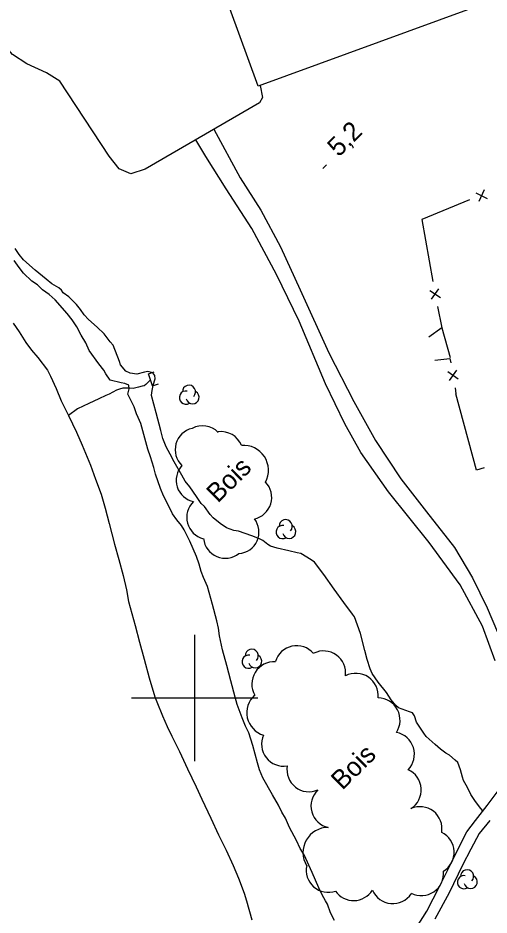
# Model space of a CAD drawing. Extents: x 381879 to 384696, y 5564785 to 5567594.
# Drawn here: x 383572 to 383646.6, y 5566565.6 to 5566707.6 of the extents above; entities that cross this region are included whole.
import ezdxf

# ---------------------------------------------------------------- set-up
doc = ezdxf.new("R2010")
doc.units = 0
for name, color, linetype in [('Niveau 19', 7, 'Continuous'), ('Niveau 2', 7, 'Continuous'), ('Niveau 26', 7, 'Continuous'), ('Niveau 3', 7, 'Continuous'), ('Niveau 31', 7, 'Continuous'), ('Niveau 37', 7, 'Continuous'), ('Niveau 4', 7, 'Continuous'), ('Niveau 44', 7, 'Continuous'), ('Niveau 52', 7, 'Continuous'), ('Niveau 61', 7, 'Continuous')]:
    doc.layers.add(name, color=color, linetype=linetype)

msp = doc.modelspace()

# ---------------------------------------------------------------- linework, layer by layer
at = {"layer": 'Niveau 19'}
for points in [[(383603.03, 5566690), (383607.21, 5566682.33), (383610.52, 5566677.19), (383613.62, 5566671.41), (383616.73, 5566664.57), (383621.28, 5566654.64), (383625.22, 5566646.9), (383628.63, 5566640.73), (383632.67, 5566634.69), (383636.74, 5566629.47), (383641.18, 5566623.8), (383644.03, 5566619.02), (383646.36, 5566614.26), (383648.86, 5566608.28)], [(383647.6, 5566605.87), (383645.59, 5566611.34), (383642.06, 5566617.87), (383637.15, 5566624.61), (383630.71, 5566632.64), (383626.34, 5566638.86), (383623.79, 5566643.39), (383620.73, 5566649.73), (383616.58, 5566659.64), (383612.99, 5566667.04), (383609.08, 5566674.28), (383605.02, 5566680.56), (383601.76, 5566685.67), (383600.18, 5566688.35)], [(383632.9, 5566560.05), (383636.76, 5566566.26), (383638.77, 5566570.13), (383640.13, 5566572.77), (383641.95, 5566576.55), (383643.13, 5566578.82), (383644.47, 5566580.6), (383646.34, 5566582.99), (383648.1, 5566585.3)], [(383646.76, 5566580.57), (383645.07, 5566578.51), (383643.76, 5566576.07), (383642.45, 5566573.52), (383640.34, 5566569.12), (383638.06, 5566564.97)]]:
    msp.add_lwpolyline(points, dxfattribs=at)
at = {"layer": 'Niveau 2'}
for points in [[(383580.07, 5566663.5), (383579.18, 5566664.13), (383578.92, 5566664.56), (383578.5, 5566664.88), (383577.39, 5566665.54), (383576.5, 5566666.25), (383574.74, 5566667.7), (383572.93, 5566669.31), (383572.23, 5566670.2), (383571.6, 5566671.15)], [(383622.16, 5566564.77), (383621.52, 5566565.99), (383621.07, 5566567.36), (383620.72, 5566567.9), (383620.2, 5566568.84), (383619.7, 5566569.95), (383618.64, 5566572.34), (383617.35, 5566575.16), (383616.74, 5566576.18), (383616.14, 5566577.44), (383615.06, 5566579.51), (383614.38, 5566580.97), (383613.84, 5566581.9), (383613.27, 5566583.03), (383612.36, 5566584.65), (383610.83, 5566587.37), (383610.26, 5566588.62), (383609.95, 5566589.7), (383609.22, 5566592.44), (383608.59, 5566594.49), (383608.06, 5566595.51), (383607.54, 5566596.84), (383606.77, 5566598.95), (383606.45, 5566600.13), (383605.77, 5566602.7), (383605.11, 5566605.13), (383604.45, 5566607.62), (383603.96, 5566609.81), (383603.81, 5566611.01), (383603.51, 5566612.2), (383602.82, 5566614.79), (383602.04, 5566617.62), (383601.41, 5566619.03), (383601.07, 5566619.99), (383600.75, 5566621.17), (383600.33, 5566622.38), (383599.26, 5566624.81), (383598.37, 5566626.6), (383597.91, 5566627.3), (383597.2, 5566628.17), (383596.52, 5566629.15), (383595.98, 5566630.25), (383595.08, 5566631.97), (383594.62, 5566633.15), (383593.83, 5566635.4), (383593.55, 5566636.47), (383593.05, 5566638.16), (383592.59, 5566639.36), (383592.27, 5566640.55), (383591.49, 5566643.45), (383591.05, 5566644.39), (383590.82, 5566644.97), (383590.46, 5566646.07), (383590.15, 5566646.61), (383589.41, 5566648.05), (383589.65, 5566648.94), (383589.57, 5566649.52), (383588.97, 5566649.76), (383588.36, 5566649.88), (383586.63, 5566650.31), (383585.93, 5566651.3), (383585.63, 5566651.86), (383584.82, 5566652.89), (383583.33, 5566654.99), (383582.79, 5566656.22), (383582.05, 5566657.43), (383581.36, 5566658.71), (383580.62, 5566659.84), (383579.82, 5566660.82), (383577.93, 5566663.01), (383576.96, 5566663.85), (383575.93, 5566664.59), (383575.12, 5566665.38), (383574.23, 5566665.97), (383572.91, 5566667.21), (383572.25, 5566668.13), (383571.45, 5566669.25)], [(383645.66, 5566582.12), (383645.33, 5566582.47), (383644.47, 5566583.59), (383643.76, 5566584.7), (383643.21, 5566585.81), (383642.6, 5566586.95), (383642.42, 5566587.45), (383642.11, 5566588.61), (383641.7, 5566589.76), (383641.28, 5566590.16), (383640.39, 5566590.92), (383639.79, 5566591.25), (383638.94, 5566591.86), (383638.08, 5566592.6), (383636.7, 5566593.88), (383636.3, 5566594.44), (383635.13, 5566596.18), (383634.81, 5566597.17), (383634.52, 5566597.61), (383634.02, 5566597.78), (383632.31, 5566598.44), (383631.86, 5566598.82), (383631.13, 5566599.7), (383630.39, 5566600.83), (383629.08, 5566602.48), (383628.15, 5566603.85), (383627.83, 5566604.59), (383627.36, 5566606.1), (383626.98, 5566607.51), (383626.27, 5566610.18), (383625.35, 5566612.81), (383625.03, 5566613.26), (383623.62, 5566615.12), (383622.13, 5566617.21), (383620.49, 5566619.54), (383618.97, 5566621.5), (383618.48, 5566621.84), (383616.83, 5566622.83), (383616.25, 5566622.98), (383614.94, 5566623.25), (383613.06, 5566623.68), (383612.04, 5566624.03), (383611.6, 5566624.28), (383610.79, 5566624.92), (383610.3, 5566625.18), (383609.08, 5566625.66), (383606.94, 5566626.37), (383606.22, 5566626.49), (383605.07, 5566626.92), (383604.05, 5566627.58), (383602.95, 5566628.49), (383602.46, 5566629.04), (383601.55, 5566630.27), (383601.03, 5566630.79), (383600.33, 5566631.89), (383599.26, 5566633.4), (383598.52, 5566634.3), (383597.96, 5566635.23), (383596.75, 5566637.37), (383596.15, 5566638.57), (383595.48, 5566639.76), (383594.99, 5566641.06), (383594.65, 5566642.33), (383593.9, 5566645.11), (383593.17, 5566647.84), (383593.24, 5566648.35), (383593.44, 5566649.48), (383593.76, 5566650.5), (383593.73, 5566651.01), (383593.38, 5566651.47), (383592.61, 5566651.64), (383592.05, 5566651.55), (383590.84, 5566651.23), (383589.78, 5566651.4), (383589.14, 5566651.7), (383588.26, 5566652.71), (383588.12, 5566653.23), (383587.13, 5566655.85), (383586.64, 5566656.38), (383585.7, 5566657.64), (383584.59, 5566658.69), (383583.21, 5566659.89), (383582.5, 5566660.61), (383581.95, 5566661.46), (383581.28, 5566662.25), (383580.07, 5566663.5)]]:
    msp.add_lwpolyline(points, dxfattribs=at)
at = {"layer": 'Niveau 26'}
for p, q in [((383592.69, 5566651.3), (383593.63, 5566651.63)), ((383593.35, 5566649.4), (383592.69, 5566651.3)), ((383593.35, 5566649.4), (383594.29, 5566649.72))]:
    msp.add_line(p, q, dxfattribs=at)
at = {"layer": 'Niveau 3'}
msp.add_line((383620.34, 5566683.78), (383620.91, 5566684.35), dxfattribs=at)
at = {"layer": 'Niveau 31'}
msp.add_lwpolyline([(383605.61, 5566709.12), (383657.84, 5566728.2), (383662.33, 5566715.9), (383610.1, 5566696.82)], close=True, dxfattribs=at)
at = {"layer": 'Niveau 37'}
for p, q in [((383644.55, 5566679.93), (383646.35, 5566679.04)), ((383645.89, 5566680.39), (383645.01, 5566678.58)), ((383643.56, 5566678.84), (383635.99, 5566675.74)), ((383635.99, 5566675.74), (383637.76, 5566665.9)), ((383637.28, 5566664.5), (383638.93, 5566663.36)), ((383637.54, 5566663.1), (383638.68, 5566664.75)), ((383640.12, 5566651.65), (383641.75, 5566650.48)), ((383640.35, 5566650.25), (383641.52, 5566651.88)), ((383641.26, 5566649.1), (383641.36, 5566648.13))]:
    msp.add_line(p, q, dxfattribs=at)
for points in [[(383638.46, 5566661.96), (383639.15, 5566658.55), (383637.08, 5566657.09)], [(383638.04, 5566653.47), (383640.43, 5566653.7), (383640.61, 5566653.04)], [(383645.87, 5566636.4), (383644.66, 5566636.03), (383641.36, 5566648.13)]]:
    msp.add_lwpolyline(points, dxfattribs=at)
at = {"layer": 'Niveau 4'}
for points in [[(383571.3, 5566659.32), (383572.25, 5566657.92), (383573.27, 5566656.27), (383574.18, 5566655.04), (383575.19, 5566653.9), (383576.73, 5566651.85), (383577.19, 5566650.94), (383578.11, 5566648.95), (383578.88, 5566647.02), (383579.82, 5566645.12), (383580.02, 5566644.7)], [(383593.02, 5566650.34), (383592.31, 5566649.59), (383592.04, 5566649.41), (383591.68, 5566649.32), (383591.14, 5566649.17), (383590.26, 5566648.98), (383589.71, 5566649.02), (383588.65, 5566649), (383588.13, 5566648.88), (383587.64, 5566648.71), (383586.5, 5566648.07), (383585.96, 5566647.87), (383584.85, 5566647.34), (383583.26, 5566646.58), (383581.47, 5566645.77), (383580.02, 5566644.7)], [(383580.02, 5566644.7), (383581.31, 5566642.04), (383582.19, 5566640), (383583.51, 5566636.83), (383584.33, 5566634.63), (383585.19, 5566632.25), (383585.83, 5566630.02), (383586.46, 5566627.6), (383587.34, 5566624.34), (383587.99, 5566621.9), (383588.67, 5566619.37), (383589.22, 5566617.08), (383589.55, 5566615.28), (383589.82, 5566614.3), (383590.58, 5566611.46), (383591.29, 5566608.81), (383592.01, 5566606.11), (383592.82, 5566603.16), (383593.69, 5566600.16), (383594.02, 5566599.38), (383594.93, 5566597.14), (383595.68, 5566595.45), (383596.41, 5566593.95), (383597.62, 5566591.5), (383598.88, 5566588.75), (383600.26, 5566585.91), (383601.15, 5566583.98), (383602.56, 5566580.96), (383603.8, 5566578.35), (383605, 5566575.88), (383606.14, 5566573.49), (383606.97, 5566571.46), (383607.86, 5566569.09), (383608.21, 5566567.9), (383609.07, 5566564.86)]]:
    msp.add_lwpolyline(points, dxfattribs=at)
at = {"layer": 'Niveau 44'}
msp.add_arc((383611.97, 5566597.65), 3.7, 131.5363, 253.3098, dxfattribs=at)
for centre, major_axis, ratio, start_param, end_param in [((383598.63, 5566647.53), (0.12, -1.04), 0.99999, 2.834597, 6.721173), ((383599.12, 5566648.45), (0.12, -1.04), 0.99999, 0.690957, 4.629966), ((383599.68, 5566647.57), (0.12, -1.04), 0.99999, 4.847526, 8.817401), ((383600.38, 5566639.28), (1.25, -3.22), 0.998771, 2.994381, 5.150465), ((383601.28, 5566639.62), (-2.9, 1.88), 0.996564, 4.492975, 5.787098), ((383604.21, 5566638.7), (-3.29, 1.06), 0.997775, 3.832963, 5.16261), ((383607.72, 5566635.99), (-3.98, -0.26), 0.999988, 2.593888, 4.722352), ((383600.54, 5566634.45), (-3.32, -0.95), 0.997449, 5.259609, 7.376939), ((383608.76, 5566631.73), (3.23, -1.25), 0.999278, 5.289832, 7.420627), ((383602.21, 5566628.55), (2.83, -1.99), 0.995292, 2.934924, 5.090471), ((383606.76, 5566626.27), (2.81, -2.01), 0.986682, 5.407172, 7.560961), ((383613.94, 5566626.25), (0.12, -1.04), 0.99999, 2.834597, 6.721173), ((383614.43, 5566627.17), (0.12, -1.04), 0.99999, 0.690957, 4.629966), ((383614.99, 5566626.29), (0.12, -1.04), 0.99999, 4.847526, 8.817401), ((383604.86, 5566625.54), (3.19, -1.34), 0.997014, 3.636787, 5.787991), ((383609.05, 5566606.66), (0.12, -1.04), 0.99999, 0.690957, 4.629966), ((383616.18, 5566604.77), (-1.67, 3.07), 0.999857, 4.924887, 7.076441), ((383620.42, 5566603.93), (-0.05, 3.5), 0.99954, 4.572551, 6.719417), ((383608.56, 5566605.74), (0.12, -1.04), 0.99999, 2.834597, 6.721173), ((383609.61, 5566605.78), (0.12, -1.04), 0.99999, 4.847526, 8.817401), ((383612.64, 5566602.16), (1.72, -3.13), 0.999985, 2.591101, 4.719276), ((383625.52, 5566600.3), (-3.58, 0.22), 0.999995, 3.119169, 5.244463), ((383629.01, 5566596.46), (3.12, 1.66), 0.999979, 5.216842, 7.342703), ((383631.27, 5566591.06), (3.54, 0.23), 0.999932, 5.458665, 7.586478), ((383614.1, 5566592.69), (2.14, -2.76), 0.999764, 3.633594, 5.791184), ((383618.13, 5566588.64), (2.75, -2.17), 0.999764, 3.634995, 5.789783), ((383632.39, 5566585.43), (2.49, 2.46), 0.999614, 4.500551, 6.65057), ((383621.93, 5566582.89), (0.93, -3.37), 0.999765, 3.632998, 5.79178), ((383635.7, 5566579.29), (-2.76, 2.13), 0.999867, 3.6333, 5.791478), ((383621.13, 5566575.53), (0.07, -3.96), 0.999996, 3.115074, 5.244028), ((383637.63, 5566575.57), (-2.6, 2.32), 0.999792, 2.834409, 4.993474), ((383621.18, 5566572.73), (3.37, 0.96), 0.999314, 2.651984, 4.771275), ((383635.93, 5566572.2), (1.85, -2.97), 0.998288, 5.249681, 7.404413), ((383642.67, 5566570.83), (0.12, -1.04), 0.99999, 2.834597, 6.721173), ((383643.16, 5566571.75), (0.12, -1.04), 0.99999, 0.690957, 4.629966), ((383643.72, 5566570.87), (0.12, -1.04), 0.99999, 4.847526, 8.817401), ((383625.19, 5566571.41), (3.49, -0.2), 0.999941, 3.804587, 5.788685), ((383631.39, 5566570.93), (3.48, -0.32), 0.999941, 3.633951, 5.790827)]:
    msp.add_ellipse(centre, major_axis=major_axis, ratio=ratio, start_param=start_param, end_param=end_param, dxfattribs=at)
at = {"layer": 'Niveau 52'}
for points in [[(383610.39, 5566696.93), (383610.77, 5566695.04), (383610.27, 5566694.21), (383592.19, 5566683.71), (383589.89, 5566682.95), (383588.06, 5566683.76), (383586.49, 5566685.74), (383578.69, 5566697.61), (383576.53, 5566698.96), (383573.43, 5566700.34), (383571.17, 5566701.81), (383568.63, 5566704.81), (383564.99, 5566711.43), (383562.65, 5566718.16), (383558.07, 5566723.89), (383552.93, 5566727.93), (383549.94, 5566731.27), (383548.84, 5566733.55), (383547.78, 5566737.55), (383558.85, 5566741.52)], [(383640.52, 5566653.8), (383639.2, 5566658.5)]]:
    msp.add_lwpolyline(points, dxfattribs=at)
at = {"layer": 'Niveau 61'}
for points in [[(383600, 5566610), (383600, 5566600), (383600, 5566590)], [(383590, 5566600), (383600, 5566600), (383610, 5566600)]]:
    msp.add_lwpolyline(points, dxfattribs=at)

# ---------------------------------------------------------------- texts
at = {"layer": 'Niveau 3'}
msp.add_text('5,2', height=3, rotation=44.7717, dxfattribs=at).set_placement((383622.83, 5566685.49))
at = {"layer": 'Niveau 44'}
for rotation, p in [(44.7707, (383603.68, 5566630.73)), (44.7717, (383623.42, 5566585.29))]:
    msp.add_text('Bois', height=3, rotation=rotation, dxfattribs=at).set_placement(p)

doc.saveas('drawing.dxf')
